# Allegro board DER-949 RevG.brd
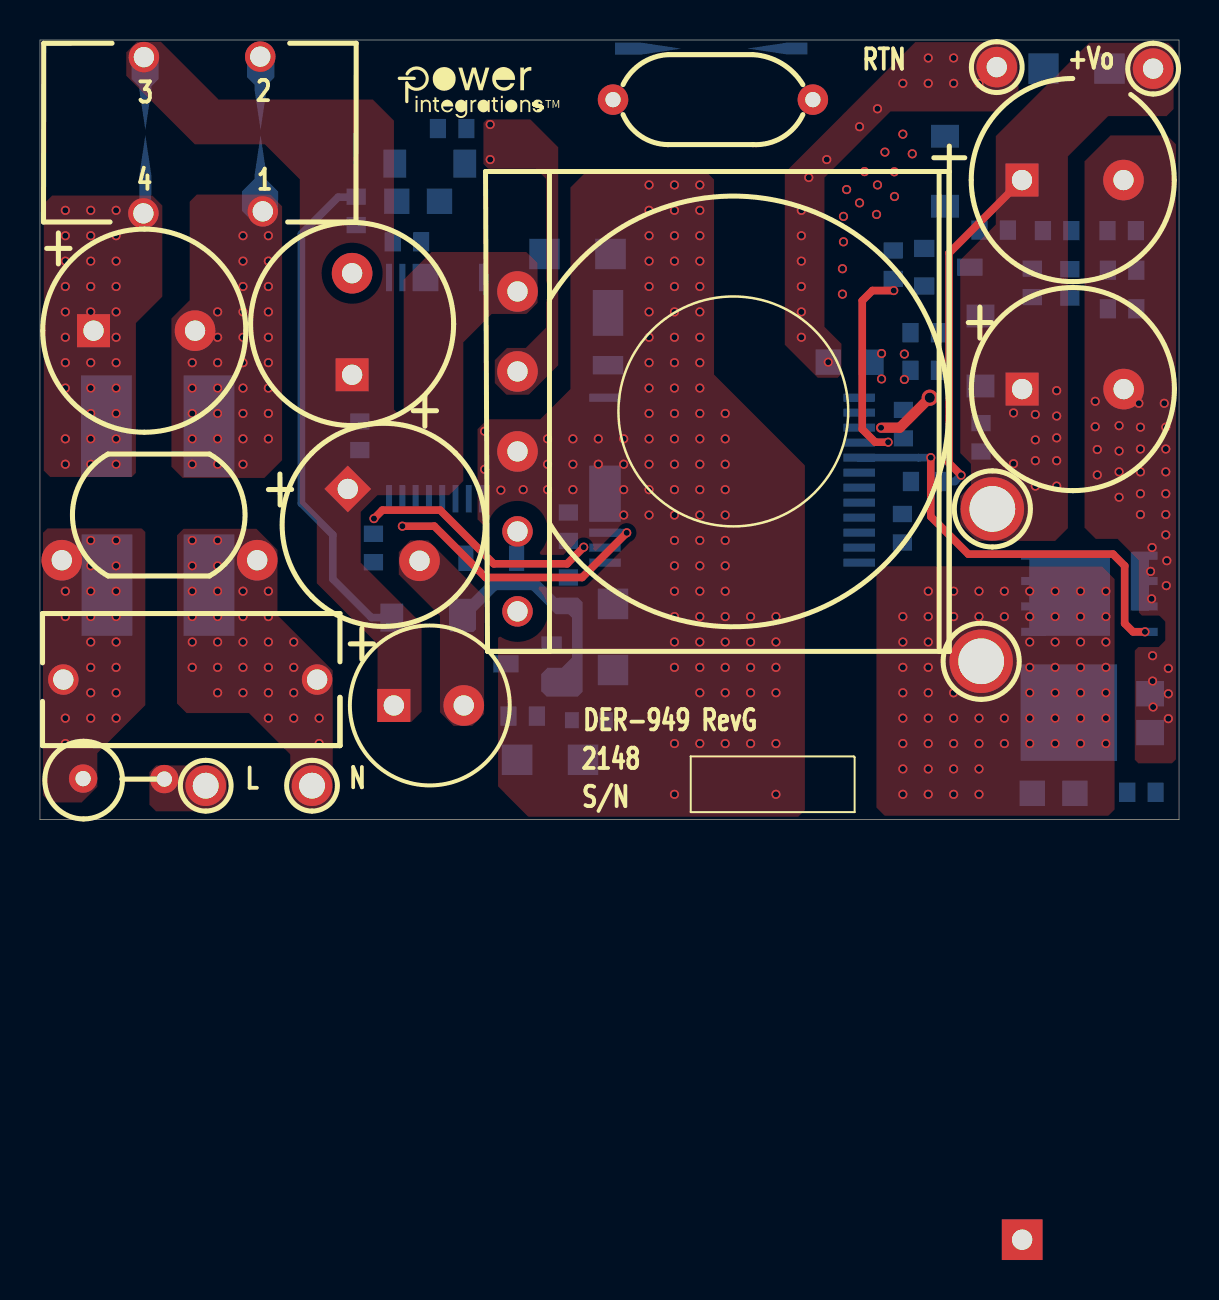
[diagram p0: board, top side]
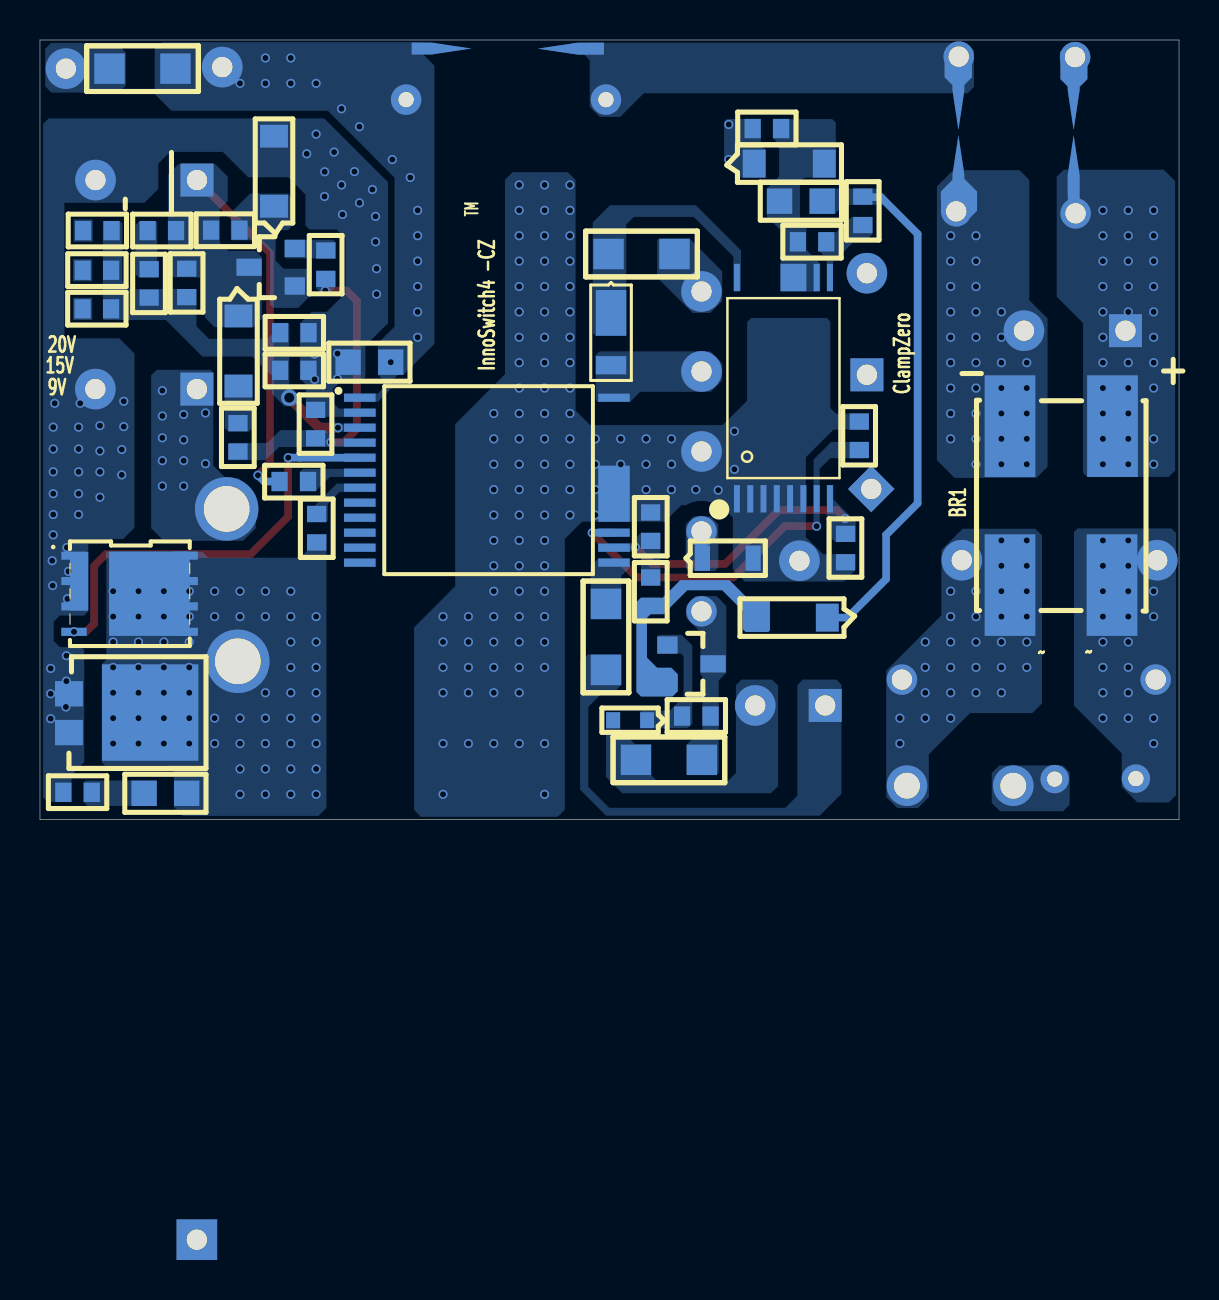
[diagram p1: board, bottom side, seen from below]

Outline 57 x 39 mm; copper layers: TOP, INNER1, INNER2, BOTTOM. Coordinates in mm from the lower left corner of the outline.
Outline path: 0,39 0,0 57,0 57,39 0,39

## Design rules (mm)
constraint set DEFAULT: min track width 0.508

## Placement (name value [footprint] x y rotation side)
BR1  Z4DGP406L-HF  [PI_SM_D_Z4D]  3.35 19.74 180 bottom
C1  150 nF  [PINPXCAPRAD475X255500040]  13.87 7.01 180 top
C2  27 uF  [PIPOLCAPCYLD400LS200040]  15.4 16.54 315 top
C3  27 uF  [PIPOLCAPCYLD400LS200040]  15.62 22.25 90 top
C4  27 uF  [PIPOLCAPCYLD400LS200040]  2.68 24.46 0 top
C5  0.47 uF  [PISMC0603]  26.44 13.94 90 bottom
C6  10 uF  [PISMC1206]  23.88 3 0 bottom
C7  2200 pF  [PINPCAPRAD9MMXLS10MM030]  28.68 36.02 0 top
C8  1000 pF  [PISMC0603]  54.41 1.37 0 bottom
C9  2.2 uF  [PISMC0603]  43.21 20.5 270 bottom
C11  330 pF  [PISMC0603]  44.98 24.36 180 bottom
C12  47 nF  [PISMC0603]  51.54 27.54 270 bottom
C13  10 uF  [PISMC1206]  53.52 37.57 180 bottom
C14  390 uF  [PIPOLCAPCYLD400LS200040]  49.14 31.99 0 top
C15  390 uF  [PIPOLCAPCYLD400LS200040]  49.15 21.54 0 top
C18  100 nF  [PISMC1206]  25.25 28.3 0 bottom
C33  4.7 nF  [PISMC0603]  19.91 34.57 0 bottom
C34  1 uF  [PISMC0805]  19.99 30.94 180 bottom
C35  100 nF  [PISMC0603]  17.65 28.91 0 bottom
C36  100 nF  [PISMC0603]  16.69 14.3 270 bottom
C44  12 uF  [PIPOLCAPCYLD3P5LS17LD40]  19.51 5.71 0 top
D1  DFLU1400-7  [PISMDDFLR120012]  28.42 25.37 90 bottom
D2  BAV21WS-7-F  [PISMSOD323]  23.85 13.08 180 bottom
D5  DSS12UTR  [PI_SM_SOD-123_12]  21.26 32.82 180 bottom
D6  HS1KFL  [PI_SM_SOD-123_12]  17.6 10.11 0 bottom
D7  V12P10-M3/86A  [PI_SM_D_TO-277A]  55.55 4.34 270 bottom
F1  6.3 A  [PI_V_AX_3-6X10_145LS200D030]  7.24 2.06 180 top
FL1  Hole_70mils  [PI_HOLE_70MIL]  47.66 15.52 0 top
FL2  Hole_70mils  [PI_HOLE_70MIL]  47.1 7.9 0 top
L1  18mH  [PI_CMC_18MH_SUMIDA]  11.15 30.1 180 top
NOREF  -  []  17.35 37.57 0 top
NOREF#2  -  []  0 0 90 top
NOREF#3  -  []  0 39 0 top
NOREF#4  -  []  -228.6 -144.78 0 top
NOREF#5  -  []  -150.78 54.23 0 top
Q1  MMBTA06LT1G  [PISMSOT23123_1]  25.6 6.86 270 bottom
Q4  AON6220  [PISMPQFN5X6B]  55.3 13.21 270 bottom
Q5  MMBTA06LT1G  [PISMSOT23123_1]  44.25 28.57 90 bottom
R9  3 k  [PISMR0603]  15.82 31.17 270 bottom
R10  47  [PISMR0603]  43.15 13.87 90 bottom
R12  2 k  [PISMR0603]  26.44 10.69 90 bottom
R13  0.0  [PISMR0805]  49.66 1.32 0 bottom
R14  100 k  [PISMR0603]  49.66 27.56 270 bottom
R15  33 K  [PISMR0603]  44.99 22.48 180 bottom
R16  0.005  [PISMR0805]  41.58 22.89 180 bottom
R19  2.7 M  [PISMR1206]  28.68 10.79 270 bottom
R22  32.4 k  [PISMR0603]  53.44 25.55 0 bottom
R23  12.7 k  [PISMR0603]  53.44 27.48 0 bottom
R24  10 k  [PISMR0603]  50.19 29.46 0 bottom
R25  1.2 k  [PISMR0603]  47.09 19.84 270 bottom
R27  8.45 k  [PISMR0603]  53.42 29.46 0 bottom
R29  75 k  [PISMR0603]  23.44 5.18 0 bottom
R31  20 k  [PISMR0603]  48.44 29.49 180 bottom
R32  47  [PISMR0603]  42.7 28.47 270 bottom
R33  30 k  [PISMR0603]  16 19.91 270 bottom
R34  100  [PISMR0603]  45.01 16.92 180 bottom
RV1  175 Vac  [PI_DISC_335X240LS200D040]  8.48 17.53 180 top
T1  EQ25  [PI_BOBBIN_EQ-25_6P]  34.7 20.42 0 top
TP1  BLK  [PITPKEYSTONE100X100]  13.61 1.7 0 top
TP2  WHT  [PITPKEYSTONE100X100]  8.29 1.7 0 top
TP10  BLK  [PITPKEYSTONE100X100]  47.88 37.64 0 top
TP11  RED  [PITPKEYSTONE100X100]  55.7 37.57 0 top
U3  CPZ1062M  [PI_SM_MINSOP16A_1]  22.12 16.05 180 bottom
U4  INN4075C-H182  [PI_IC_INSOP_24D_IPC]  41 21.11 180 bottom
VR1  MMSZ5250B-7-F  [PI_SM_SOD-123_12]  47.07 25.2 270 bottom
VR4  EDZVT2R10B  [PI_SM_D_SSMINI2P]  26.62 4.98 0 bottom
VR5  MMSZ5232B-7-F  [PI_SM_SOD-123_12]  45.29 30.68 90 bottom

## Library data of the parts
BR1 = DISCRETE BRIDGE_+~~-
C1 C5 C7 C8 C11-C13 C18 = CAP NP
C2-C4 = CAP POL: alternate symbols: (pipolcapclyd400x675ls200040h)
C6 = CAP NP: alternate symbols: (pismc1206_1)
C9 = CAP NP: alternate symbols: (pismc0603_1)
C14 C15 = CAP POL: alternate symbols: (pipolcapclyd400x530ls200030h)
C33-C36 = CAP NP: room: 2
C44 = CAP POL: alternate symbols: (pipolcapcyld3p5ls17ld40H)
D1 D2 = DIODE
D5 = DIODE SCHOTTKY
D6 = DIODE: room: 2
D7 = DIODE SCHOTTKY_TO-277A
F1 = FUSE: alternate symbols: (pi_axial_3_6x10_145ls500d030)
FL1 FL2 = FlyingLead
L1 = TORRID 4P_12_43a: alternate symbols: (pi_CMC_18mH_SumidaW,pi_CMC_18mH_Sumida_H,pi_CMC_18mH_SumidaSF)
Q1 Q5 = NPN_BEC: room: 2
Q4 = FET_N_SGD_123_4_5678
R9 R29 R31 R33 R34 = R: room: 2
R10 = R: alternate symbols: (pismr0603_1)
R12 R32 = R: alternate symbols: (pismr0603_1); room: 2
R13 = R: alternate symbols: (pismr0805_1)
R14-R16 R19 R22-R25 R27 = R
RV1 = VARISTOR
T1 = BEQ25_6P
TP1 TP10 = TESTPOINT: alternate symbols: (TP_TH_CR2_D1_1)
TP2 TP11 = TESTPOINT
U3 = ClampZeroMinSOP16: room: 2
U4 = MinnoPriSecCZ: alternate symbols: (pi_ic_insop_24d,PI_IC_INSOP24B)
VR1 = DIODE_ZENER
VR4 VR5 = DIODE_ZENER: room: 2

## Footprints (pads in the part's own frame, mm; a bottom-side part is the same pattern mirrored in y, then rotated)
PI_BOBBIN_EQ-25_6P
  rect 2.032x2.032 hole 1.016: 1(14.453,-41.427)
  round 2.032 hole 1.016: 2(-10.8,6) 3(-10.8,2) 4(-10.8,-2)
  round 1.524 hole 1.016: 5(-10.8,-6) 6(-10.8,-10)
PI_CMC_18MH_SUMIDA
  round 1.524 hole 1.016: 1(0,-0.33) 2(0.127,-8.068) 3(5.949,-8.043) 4(5.975,-0.229)
PI_DISC_335X240LS200D040
  round 2.032 hole 1.016: 1(-2.388,4.547) 2(7.391,4.547)
PI_HOLE_70MIL
  round 3.175 hole 2.286: 1(0,0.025)
PI_IC_INSOP_24D_IPC
  rect 1.58x0.41 smd: 1(0,0) 2(0,-0.75) 3(0,-1.5) 4(0,-2.25) 5(0,-3) 6(0,-3.75) 7(0,-4.5) 8(0,-5.25) 9(0,-6) 10(0,-6.75) 11(0,-7.5) 12(0,-8.25) 13(12.72,-8.25) 14(12.72,-7.5) 15(12.72,-6.75) 24(12.72,0)
  rect 1.58x2.81 smd: 16(12.72,-4.8)
PI_SM_D_SSMINI2P
  rect 0.699x0.8 smd: 1(0,0) 2(1.7,0)
PI_SM_D_TO-277A
  rect 1.27x1.397 smd: 1(-0.015,0) 2(-1.956,0)
  rect 4.826x4.826 smd: 3(-1.016,4.064)
PI_SM_D_Z4D
  rect 2.54x5.08 smd: 1(0.025,-0.051) 2(0,-8.001) 3(-5.105,-8.001) 4(-5.105,-0.051)
PI_SM_MINSOP16A_1
  rect 0.3x1.37 smd: 1(0,0) 2(0.665,0) 3(1.33,0) 4(1.995,0) 5(2.66,0) 6(3.325,0) 7(3.99,0) 8(4.655,0) 9(4.655,11.067) 10(3.99,11.067) 16(0,11.067)
  rect 1.292x1.37 smd: 11(2.829,11.067)
PI_SM_SOD-123_12
  rect 1.143x1.397 smd: 1(0,0) 2(3.505,0)
PI_V_AX_3-6X10_145LS200D030
  round 1.422 hole 0.762: 1(1.016,0.025) 2(5.08,0)
PINPCAPRAD9MMXLS10MM030
  round 1.524 hole 0.762: 1(0,0) 2(10,0)
PINPXCAPRAD475X255500040
  round 1.524 hole 1.016: 1(0,0) 2(12.7,0)
PIPOLCAPCYLD3P5LS17LD40
  rect 1.651x1.651 hole 1.016: 1(-1.8,0)
  round 2.032 hole 1.016: 2(1.7,0)
PIPOLCAPCYLD400LS200040
  rect 1.651x1.651 hole 1.016: 1(0,0)
  round 2.032 hole 1.016: 2(5.08,0)
PISMC0603
  rect 0.813x0.965 smd: 1(0,0) 2(1.422,0)
PISMC0805
  rect 1.27x1.27 smd: 1(0,0) 2(2.134,0)
PISMC1206
  rect 1.524x1.524 smd: 1(0,0) 2(3.302,0)
PISMDDFLR120012
  rect 2.286x1.524 smd: 1(-0.025,0)
  rect 0.914x1.524 smd: 2(-2.642,0)
PISMPQFN5X6B
  rect 0.406x1.27 smd: 1(0,0) 2(1.27,0) 3(2.54,0) 4(3.81,0)
  rect 0.406x1.219 smd: 5(3.81,5.588) 6(2.54,5.588) 7(1.27,5.588) 8(0,5.588)
PISMR0603
  rect 0.813x0.965 smd: 1(0,0) 2(1.422,0)
PISMR0805
  rect 1.27x1.27 smd: 1(0,0) 2(2.134,0)
PISMR1206
  rect 1.524x1.524 smd: 1(0,0) 2(3.302,0)
PISMSOD323
  rect 0.762x1.27 smd: 1(0,0) 2(2.54,0)
PISMSOT23123_1
  rect 0.864x1.016 smd: 1(-1.88,0) 2(0,0)
  rect 0.864x1.27 smd: 3(-0.94,2.286)
PITPKEYSTONE100X100
  round 2.032 hole 1.016: 1(0,0)

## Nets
GND_POWER: C8.2 C9.1 C11.2 C14.2 C15.2 D7.1 D7.2 Q4.1 Q4.2 Q4.3(S3) R15.2 R16.1 U4.2 VR5.2
GND_SIGNAL: C2.2 C3.2 C5.2 C6.2 C7.1 C36.2 C44.2 D2.2 L1.2 R33.1 T1.4 U3.1 U3.2 U3.3 U3.4 U3.5 U3.6 U4.16 VR4.2
N11018979: C13.1 C14.1 C15.1 FL1.1 Q5.3 R14.1 R24.1 R31.1 R34.1 TP11.1 VR1.1
N11018991: C7.2 C13.2 R16.2 TP10.1 U4.1
N11019027: D7.3(CATHODE) FL2.1 Q4.5 Q4.6 Q4.7 Q4.8 R10.1 R13.1
N11019153: C18.2 D1.1 U3.16
N11019263: BR1.4 C4.2 L1.1
N11019397: BR1.3(AC2) C1.1 RV1.1 TP1.1
N11019401: C8.1 R13.2
N11019625: C2.1 C3.1 C18.1 C44.1 L1.3 R19.2 T1.2
N11019673: BR1.2 C1.2 F1.2 RV1.2
N11019681: BR1.1 C4.1 L1.4
N11019743: C11.1 C12.2 R14.2 R15.1 R22.1 R23.1 R27.1 U4.3
N11020753: C33.2 D1.2 D5.1 T1.3 U4.24
N11026403: F1.1 TP2.1
N11096846: R22.2
N11102317: R23.2
N11111738: C12.1 R24.2
N11114484: R25.1 VR1.2
N12700264: R27.2
N12705759: D2.1 T1.5
N12706342: C6.1 Q1.3 R29.1 T1.6
N12717194: R19.1 U4.13
N12732567: Q4.4 U4.5
N12733996: R10.2 U4.7
N12734050: C9.2 R25.2 R32.2 U4.4
N12734238: R34.2 U4.6
N12735016: C5.1 C36.1 R12.2 U3.8 U4.14
N12739704: Q1.1 R29.2 VR4.1
N12739734: D6.2 Q1.2(EMITTER) R12.1
N13029584: Q5.1 R31.2 VR5.1
N13029614: Q5.2(EMITTER) R32.1
N13041937: C33.1 C34.1 C35.2 D5.2 U3.10 U3.11
N13042085: C35.1 R9.2 U3.9
N13042117: C34.2 D6.1 R9.1
N13042133: R33.2 U3.7 U4.15

Pads without a net: T1 1; U4 8 9 10 11 12

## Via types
v1: diameter 0.457, hole 0.305, TOP to BOTTOM, 362 vias
v2: diameter 0.813, hole 0.508, TOP to BOTTOM, 1 via

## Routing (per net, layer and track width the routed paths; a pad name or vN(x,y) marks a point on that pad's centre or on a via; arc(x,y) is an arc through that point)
GND_POWER:
  vias: v1(40.21,30.18) v1(40.21,28.91) v1(40.16,27.56) v1(40.16,26.29) v1(40.36,31.52) v1(41.01,30.85) v1(41.26,32.42) v1(41.91,31.75) v1(41.86,30.27) v1(42.11,23.32) v1(42.11,22.05) v1(42.28,33.39) v1(42.75,32.41) v1(42.76,31.17) v1(43.18,34.29) v1(43.26,23.29) v1(43.26,22.02) v1(43.65,33.31) v1(52.81,20.93) v1(52.81,19.66) v1(52.91,18.52) v1(52.91,17.25) v1(54,19.71) v1(54,18.44) v1(54,17.4) v1(54,16.13) v1(54.99,20.83) v1(55.07,19.63) v1(55.07,18.54) v1(55.07,17.4) v1(55.07,16.31) v1(55.07,15.27) v1(55.58,12.42) v1(55.63,11.05) v1(55.65,13.61) v1(55.68,8.2) v1(55.68,6.93) v1(55.7,5.64) v1(56.26,20.83) v1(56.34,19.63) v1(56.34,18.54) v1(56.34,17.4) v1(56.34,16.31) v1(56.34,15.27) v1(56.34,14.25) v1(56.39,12.95) v1(56.36,11.71) v1(56.46,7.57) v1(56.46,6.3) v1(56.46,5.05)
GND_SIGNAL:
  vias: v1(22.25,19.43) v1(22.25,17.53) v1(23.06,16.48) v1(24.18,16.51) v1(25.4,19.05) v1(25.4,17.78) v1(25.4,16.51) v1(26.67,19.05) v1(26.67,17.78) v1(26.67,16.51) v1(27.94,19.05) v1(27.94,17.78) v1(29.21,19.05) v1(29.21,17.78) v1(29.21,16.51) v1(29.21,15.24) v1(30.48,31.75) v1(30.48,30.48) v1(30.48,29.21) v1(30.48,27.94) v1(30.48,26.67) v1(30.48,25.4) v1(30.48,24.13) v1(30.48,22.86) v1(30.48,21.59) v1(30.48,20.32) v1(30.48,19.05) v1(30.48,17.78) v1(30.48,16.51) v1(30.48,15.24) v1(31.75,31.75) v1(31.75,30.48) v1(31.75,29.21) v1(31.75,27.94) v1(31.75,26.67) v1(31.75,25.4) v1(31.75,24.13) v1(31.75,22.86) v1(31.75,21.59) v1(31.75,20.32) v1(31.75,19.05) v1(31.75,17.78) v1(31.75,16.51) v1(31.75,15.24) v1(31.75,13.97) v1(31.75,12.7) v1(31.75,11.43) v1(31.75,10.16) v1(31.75,8.89) v1(31.75,7.62) v1(31.75,3.81) v1(31.75,1.27) v1(33.02,31.75) v1(33.02,30.48) v1(33.02,29.21) v1(33.02,27.94) v1(33.02,26.67) v1(33.02,25.4) v1(33.02,24.13) v1(33.02,22.86) v1(33.02,21.59) v1(33.02,20.32) v1(33.02,19.05) v1(33.02,17.78) v1(33.02,16.51) v1(33.02,15.24) v1(33.02,13.97) v1(33.02,12.7) v1(33.02,11.43) v1(33.02,10.16) v1(33.02,8.89) v1(33.02,7.62) v1(33.02,6.35) v1(33.02,3.81) v1(34.29,20.32) v1(34.29,19.05) v1(34.29,17.78) v1(34.29,16.51) v1(34.29,15.24) v1(34.29,13.97) v1(34.29,12.7) v1(34.29,11.43) v1(34.29,10.16) v1(34.29,8.89) v1(34.29,7.62) v1(34.29,6.35) v1(34.29,3.81) v1(35.56,10.16) v1(35.56,8.89) v1(35.56,7.62) v1(35.56,6.35) v1(35.56,3.81) v1(36.83,10.16) v1(36.83,8.89) v1(36.83,7.62) v1(36.83,6.35) v1(36.83,3.81) v1(36.83,1.27)
N11018979: length 17.7
  TOP w0.381: C14.1 45.49,28.34 45.49,17.83 v1(46.09,17.23)
  BOTTOM w0.381: R34.1 45.78,16.92 v1(46.09,17.23)
  vias: v1(48.72,20.35) v1(48.72,17.81) v1(49.81,20.27) v1(49.81,19) v1(49.81,17.96) v1(49.81,16.69) v1(50.88,21.46) v1(50.88,20.19) v1(50.88,19.1) v1(50.88,17.96) v1(50.88,16.69)
N11018991:
  vias: v1(38.1,30.48) v1(38.1,29.21) v1(38.1,27.94) v1(38.1,26.67) v1(38.1,25.4) v1(38.1,24.13) v1(38.47,32.12) v1(39.37,33.02) v1(39.45,22.89) v1(41.01,34.66) v1(41.91,35.56) v1(43.18,36.83) v1(44.45,38.1) v1(44.45,36.83) v1(45.72,38.1) v1(45.72,36.83) v1(46.99,36.83)
N11019027:
  vias: v1(43.18,10.16) v1(43.18,8.89) v1(43.18,7.62) v1(43.18,6.35) v1(43.18,5.08) v1(43.18,3.81) v1(43.18,2.54) v1(43.18,1.27) v1(44.45,11.43) v1(44.45,10.16) v1(44.45,8.89) v1(44.45,7.62) v1(44.45,6.35) v1(44.45,5.08) v1(44.45,3.81) v1(44.45,2.54) v1(44.45,1.27) v1(45.72,11.43) v1(45.72,10.16) v1(45.72,6.35) v1(45.72,5.08) v1(45.72,3.81) v1(45.72,2.54) v1(45.72,1.27) v1(46.99,11.43) v1(46.99,10.16) v1(46.99,5.08) v1(46.99,3.81) v1(46.99,2.54) v1(46.99,1.27) v1(48.26,11.43) v1(48.26,10.16) v1(48.26,5.08) v1(48.26,3.81) v1(49.53,11.43) v1(49.53,10.16) v1(49.53,8.89) v1(49.53,7.62) v1(49.53,6.35) v1(49.53,5.08) v1(49.53,3.81) v1(50.8,11.43) v1(50.8,10.16) v1(50.8,8.89) v1(50.8,7.62) v1(50.8,6.35) v1(50.8,5.08) v1(50.8,3.81) v1(52.07,11.43) v1(52.07,10.16) v1(52.07,8.89) v1(52.07,7.62) v1(52.07,6.35) v1(52.07,5.08) v1(52.07,3.81) v1(53.34,11.43) v1(53.34,10.16) v1(53.34,8.89) v1(53.34,7.62) v1(53.34,6.35) v1(53.34,5.08) v1(53.34,3.81)
N11019263:
  vias: v1(7.62,22.86) v1(7.62,21.59) v1(7.62,20.32) v1(7.62,19.05) v1(7.62,17.78) v1(8.89,25.4) v1(8.89,24.13) v1(8.89,22.86) v1(8.89,21.59) v1(8.89,20.32) v1(8.89,19.05) v1(8.89,17.78) v1(10.16,29.21) v1(10.16,27.94) v1(10.16,26.67) v1(10.16,25.4) v1(10.16,24.13) v1(10.16,22.86) v1(10.16,21.59) v1(10.16,20.32) v1(10.16,19.05) v1(10.16,17.78) v1(11.43,29.21) v1(11.43,27.94) v1(11.43,26.67) v1(11.43,25.4) v1(11.43,24.13) v1(11.43,22.86) v1(11.43,21.59) v1(11.43,20.32) v1(11.43,19.05)
N11019397:
  vias: v1(7.62,13.97) v1(7.62,12.7) v1(7.62,11.43) v1(7.62,10.16) v1(7.62,8.89) v1(7.62,7.62) v1(8.89,13.97) v1(8.89,12.7) v1(8.89,11.43) v1(8.89,10.16) v1(8.89,8.89) v1(8.89,7.62) v1(8.89,6.35) v1(10.16,11.43) v1(10.16,10.16) v1(10.16,8.89) v1(10.16,7.62) v1(10.16,6.35) v1(11.43,11.43) v1(11.43,10.16) v1(11.43,8.89) v1(11.43,7.62) v1(11.43,6.35) v1(11.43,5.08) v1(12.7,8.89) v1(12.7,7.62) v1(12.7,6.35) v1(12.7,5.08) v1(13.97,5.08) v1(13.97,3.81)
N11019673:
  vias: v1(1.27,11.43) v1(1.27,10.16) v1(1.27,5.08) v1(1.27,3.81) v1(2.54,13.97) v1(2.54,12.7) v1(2.54,11.43) v1(2.54,10.16) v1(2.54,8.89) v1(2.54,7.62) v1(2.54,6.35) v1(2.54,5.08) v1(3.81,13.97) v1(3.81,12.7) v1(3.81,11.43) v1(3.81,10.16) v1(3.81,8.89) v1(3.81,7.62) v1(3.81,6.35) v1(3.81,5.08)
N11019681:
  vias: v1(1.27,30.48) v1(1.27,29.21) v1(1.27,27.94) v1(1.27,26.67) v1(1.27,25.4) v1(1.27,24.13) v1(1.27,22.86) v1(1.27,21.59) v1(1.27,19.05) v1(1.27,17.78) v1(2.54,30.48) v1(2.54,29.21) v1(2.54,27.94) v1(2.54,26.67) v1(2.54,25.4) v1(2.54,22.86) v1(2.54,21.59) v1(2.54,20.32) v1(2.54,19.05) v1(2.54,17.78) v1(3.81,30.48) v1(3.81,29.21) v1(3.81,27.94) v1(3.81,26.67) v1(3.81,25.4) v1(3.81,24.13) v1(3.81,22.86) v1(3.81,21.59) v1(3.81,20.32) v1(3.81,19.05) v1(3.81,17.78)
N11019743: length 3.1
  TOP w0.508: v2(44.53,21.11) 43.03,19.61 v1(42.09,19.61)
N11020753:
  vias: v1(22.53,34.77) v1(22.53,33.02)
N12732567: length 21.3
  TOP w0.381: v1(44.58,18.11) 44.58,15.16 46.46,13.28 53.7,13.28 54.28,12.7 54.28,9.82 54.7,9.4 v1(55.3,9.4)
  BOTTOM w0.381: U4.5 43.98,18.11 43.98,18.11 v1(44.58,18.11)
N12734050: length 9.8
  TOP w0.381: v1(42.44,18.88) 41.8,18.88 41.15,19.53 41.15,25.96 41.66,26.47 v1(42.72,26.47)
N12735016: length 12.1
  TOP w0.381: v1(16.71,15.06) 17.14,15.48 20.02,15.48 22.71,12.8 26.38,12.8 v1(27.21,13.63)
N13042117: length 25.2
  BOTTOM w0.381: D6.1 16.59,10.11 14.66,12.04 14.66,14.25 13.08,15.82 13.08,29.3 14.92,31.14 15.8,31.14 R9.1
N13042133: length 14.3
  TOP w0.381: v1(29.36,14.35) 27.13,12.12 22.3,12.12 19.74,14.68 v1(18.14,14.68)
  BOTTOM w0.381: U4.15 29.36,14.36 v1(29.36,14.35)

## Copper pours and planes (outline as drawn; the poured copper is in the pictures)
GND_POWER on BOTTOM (solid shape): 55.5,10.46 54.58,10.46 54.58,13.39 55.5,13.39
GND_POWER on TOP: 56.4,34.23 56.85,33.78 56.85,3.02 56.64,2.82 54.97,2.82 54.79,3 54.79,8.46 54.97,8.64 55.98,8.64 56.31,8.97 56.31,9.91 56.01,10.21 55.14,10.21 54.99,10.36 54.99,12.98 53.92,14.05 52.83,14.05 52.27,14.61 52.27,32.93 53.57,34.23
GND_POWER on BOTTOM: 42.77,35.08 56.57,35.08 56.85,34.8 56.85,1.12 56.62,0.89 55.42,0.89 55.42,2.24 54.79,2.88 54.79,8.48 54.94,8.64 56.01,8.64 56.31,8.94 56.31,9.91 56.01,10.21 54.79,10.21 54.58,10.42 54.58,13.83 54.37,14.04 52.84,14.04 52.27,14.61 52.27,23.32 53.04,24.08 55.78,24.08 55.78,30.86 51.77,30.86 51.08,31.55 51.08,32.82 50.5,33.4 47.85,33.4 46.58,32.13 44.58,32.13 43.71,31.27 43.71,29.72 43.51,29.51 42.14,29.51 41.71,29.08 41.71,26.34 42.65,25.4 43.41,25.4 43.99,24.81 43.99,22.05 43.97,22.05 43.69,21.77 43.69,20.15 40.21,20.15 40.21,20.56 42.05,20.56 42.34,20.85 42.34,21.54 41.99,21.89 40.97,21.89 40.72,22.15 40.72,23.7 39.59,24.83 39.59,31.89
GND_POWER on INNER1: 45.77,35.1 45.77,35.09 45.95,34.92 45.95,33.33 41.7,29.08 41.7,26.34 42.64,25.4 43.41,25.4 43.98,24.83 43.98,22.06 43.49,21.56 41.33,21.56 40.71,22.18 40.71,23.7 39.58,24.83 39.58,31.91 42.77,35.1
GND_POWER on INNER1: 54.97,8.64 56,8.64 56.31,8.95 56.31,9.91 56.01,10.21 54.8,10.21 54.58,10.43 54.58,14.28 54.38,14.47 52.66,14.47 52.27,14.86 52.27,32.93 53.57,34.23 56.4,34.23 56.85,33.79 56.85,3.02 56.64,2.82 54.96,2.82 54.79,3 54.79,8.46
GND_POWER on INNER2: 39.59,31.91 42.77,35.1 45.76,35.1 45.94,34.92 45.94,33.32 41.7,29.08 41.7,26.34 42.64,25.4 43.41,25.4 43.99,24.82 43.99,22.07 43.48,21.56 41.3,21.56 40.72,22.15 40.72,23.7 39.59,24.83
GND_POWER on INNER2: 56.85,33.79 56.85,3.02 56.65,2.82 54.85,2.82 54.79,2.88 54.79,8.41 54.79,8.48 54.94,8.64 56,8.64 56.31,8.95 56.31,9.91 56.01,10.21 54.8,10.21 54.58,10.43 54.58,12.56 54.58,12.56 54.58,14.28 54.39,14.47 52.67,14.47 52.27,14.87 52.27,32.92 53.58,34.23 56.41,34.23
GND_SIGNAL on BOTTOM (solid shape): 32.08,38.57 30.08,38.27 30.1,38.26 28.79,38.26 28.78,38.28 28.78,38.86 28.78,38.87 30.08,38.87
GND_SIGNAL on BOTTOM (solid shape): 11.73,38.43 11.73,37.13 11.34,36.74 11.34,36.5 11.04,34.5 10.74,36.5 10.74,36.75 10.36,37.13 10.36,38.4 10.57,38.61 11.56,38.61
GND_SIGNAL on TOP: 22.23,5.29 21.63,4.69 20.7,4.69 20.02,5.38 20.02,10.2 17.95,12.27 17.95,13.39 18.54,13.97 19.43,13.97 22.23,11.17
GND_SIGNAL on TOP: 25.03,20.03 26.54,21.54 26.54,31.62 27.3,32.38 33.37,32.38 33.73,32.02 33.73,22.26 38.28,17.72 38.28,0.48 37.95,0.15 24.43,0.15 22.92,1.66 22.92,14 21.89,15.02 21.89,19.53 22.39,20.03
GND_SIGNAL on BOTTOM: 29.49,35.65 29.49,38 29.79,38.3 29.79,38.71 29.64,38.86 10.63,38.86 10.26,38.49 10.26,36.65 10.58,36.33 26.78,36.33 27.97,35.15 28.99,35.15
GND_SIGNAL on BOTTOM: 30.2,20.47 30.2,32 30.58,32.38 33.35,32.38 33.73,32 33.73,22.28 36.22,19.79 36.22,11.68 38.28,9.63 38.28,0.48 37.95,0.15 31.08,0.15 30.73,0.5 30.73,14.05 29.87,14.91 25.73,14.91 24.9,15.74 22.95,15.74 22.33,15.11 22.33,12.52 21.72,11.91 16.76,11.91 16.2,12.47 16.2,13.28 17.82,13.28 18.68,14.15 18.68,18.12 17.42,19.38 17.42,19.38 17.29,19.51 15.52,19.51 15.52,20.32 17.17,20.32 17.45,20.6 17.45,24.92 17.63,25.1 21.42,25.1 21.62,24.9 21.62,20.95 22.84,19.74 29.46,19.74
GND_SIGNAL on BOTTOM: 20.37,7.01 21.89,7.01 22.17,6.73 22.17,2.34 22.66,1.85 26.03,1.85 26.42,2.23 26.42,3.76 27.2,3.76 27.97,4.52 27.97,5.38 28.65,5.38 28.68,5.36 28.68,2.48 28.68,2.47 28.68,2.15 27.86,1.32 20.42,1.32 20.07,1.68 20.07,6.71
GND_SIGNAL on INNER1: 33.73,22.28 38.28,17.73 38.28,0.48 37.95,0.15 20.75,0.15 20.02,0.88 20.02,10.21 19.48,10.74 19.41,10.82 17.95,12.28 17.95,12.28 17.95,13.4 18.54,13.98 18.54,13.98 18.73,14.17 18.73,15.13 18.91,15.32 21.34,15.32 22.1,16.08 22.1,20.24 22.39,20.54 25.54,20.54 26.09,21.09 26.09,31.78 26.7,32.39 33.35,32.39 33.73,32.01
GND_SIGNAL on INNER2: 10.6,38.91 20.29,38.91 20.31,38.9 28.66,38.9 29.47,38.09 29.47,35.6 29.01,35.14 27.94,35.14 27.24,35.84 21.97,35.84 21.61,35.48 21.61,20.96 22.04,20.54 25.54,20.54 26.09,21.09 26.09,31.77 26.7,32.38 33.35,32.38 33.73,32.01 33.73,22.27 38.28,17.73 38.28,0.51 37.92,0.15 20.7,0.15 20.02,0.83 20.02,10.16 17.95,12.23 17.95,13.38 17.95,13.38 18.73,14.16 18.73,15.14 18.21,15.66 18.21,23.65 16.64,25.22 15.04,25.22 13.97,26.29 13.97,28.35 14.01,28.38 14.01,33.31 10.23,37.09 10.23,38.54
N11018979 on TOP: 47.83,34.19 52.5,38.86 56.46,38.86 56.73,38.6 56.73,35.55 56.38,35.19 53.45,35.19 51.44,33.17 51.44,14.58 50.8,13.94 46.89,13.94 46.05,14.78 46.05,16.18 46.58,16.71 46.58,17.81 46.05,18.34 46.05,27.99 47.83,29.77
N11018979 on BOTTOM: 46.2,28.45 47.57,28.45 48.01,28.88 48.01,30.53 47.6,30.94 47.6,32.16 48.23,32.79 50.06,32.79 50.6,32.26 50.6,27.43 50.29,27.13 49.3,27.13 49.3,27.13 49.03,27.13 48.74,26.84 48.74,25.12 48.26,24.64 46.3,24.64 45.9,25.04 45.9,28.14
N11018979 on BOTTOM: 47.04,17.07 47.68,17.07 48.33,17.72 48.33,22.37 48.47,22.5 51.16,22.5 51.44,22.23 51.44,14.58 50.81,13.95 46.83,13.95 46.2,14.58 46.2,16.23
N11018979 on BOTTOM: 53.06,36.37 52.7,36.72 52.7,38.37 53.19,38.85 56.44,38.85 56.74,38.56 56.74,36.68 56.43,36.37
N11018979 on INNER1: 56.73,35.55 56.38,35.19 53.43,35.19 51.43,33.19 51.43,14.55 50.82,13.94 46.88,13.94 46.05,14.78 46.05,16.18 46.58,16.72 46.58,17.81 46.05,18.34 46.05,30.16 47.82,31.93 47.82,34.18 52.5,38.86 56.46,38.86 56.73,38.59
N11018979 on INNER2: 47.83,34.21 52.47,38.85 56.44,38.85 56.73,38.57 56.73,35.54 56.38,35.19 53.43,35.19 51.67,33.43 51.67,33.42 51.43,33.18 51.43,14.56 50.82,13.95 46.88,13.95 46.04,14.78 46.04,16.17 46.58,16.71 46.58,17.81 46.05,18.34 46.05,30.15 47.83,31.92
N11018991 on BOTTOM (solid shape): 38.4,38.27 37.4,38.27 35.4,38.57 37.4,38.87 38.4,38.87
N11018991 on TOP: 48.96,36.46 48.96,38.34 48.41,38.89 43.8,38.89 37.27,32.36 37.27,23.75 38.92,22.1 39.92,22.1 40.11,22.29 40.11,23.8 39.26,24.65 39.26,32.12 42.57,35.43 47.93,35.43
N11018991 on BOTTOM: 39.26,32.12 42.6,35.46 50.42,35.46 51.26,36.3 51.26,38.53 50.9,38.89 37.82,38.89 37.82,38.28 37.26,37.72 37.26,23.8 38.8,22.25 39.09,22.25 39.37,21.97 39.37,21.62 40.08,20.9 41.79,20.9 41.79,20.9 41.79,21.31 41.79,21.31 40.11,21.31 39.8,21.62 39.8,21.97 40.09,22.26 40.09,23.82 39.26,24.66
N11018991 on INNER1: 39.26,32.12 42.57,35.43 47.93,35.43 48.96,36.46 48.96,38.35 48.44,38.86 43.81,38.86 37.27,32.33 37.27,23.75 38.92,22.1 39.92,22.1 40.11,22.29 40.11,23.81 39.26,24.65
N11018991 on INNER2: 39.29,24.62 39.26,24.66 39.26,32.12 42.57,35.43 47.93,35.43 48.97,36.47 48.97,38.34 48.44,38.86 43.81,38.86 37.26,32.31 37.26,23.78 38.89,22.16 39.99,22.16 40.09,22.26 40.09,23.82
N11019027 on BOTTOM (solid shape): 53.54,9.19 49.5,9.19 49.5,13.41 53.54,13.41
N11019027 on TOP: 53.14,12.67 53.77,12.04 53.77,0.51 53.47,0.2 42.27,0.2 41.86,0.61 41.86,12.19 42.34,12.67
N11019027 on BOTTOM: 53.9,7.78 53.9,2.86 53.74,2.7 50.54,2.7 50.29,2.45 50.29,0.64 49.85,0.19 43.07,0.19 42.66,0.59 42.66,14.28 43.64,14.28 43.64,13.44 43.97,13.11 48.59,13.11 48.9,13.41 53.68,13.41 53.68,8
N11019027 on INNER1: 41.86,11.78 42.28,12.2 53.61,12.2 53.77,12.04 53.77,0.51 53.47,0.2 53.47,0.2 42.27,0.2 41.86,0.61
N11019027 on INNER2: 41.86,0.61 41.86,11.78 42.28,12.2 53.62,12.2 53.78,12.04 53.78,0.5 53.48,0.2 42.26,0.2
N11019153 on BOTTOM: 24.18,30.73 28.47,30.73 29.34,29.87 29.34,24.36 29.18,24.21 27.66,24.21 27.66,24.23 27.66,29.77 27.28,30.15 24.28,30.15 22.3,28.17 22.3,26.49 22.25,26.44 21.97,26.44 21.92,26.49 21.92,28.47
N11019263 on BOTTOM (solid shape): 11.34,32.24 11.34,32 11.89,31.46 11.92,31.43 11.92,30.99 11.91,30.99 11.91,30.56 11.48,30.12 10.44,30.12 10.11,30.46 10.11,31.42 10.74,32.05 10.74,32.24 11.04,34.24
N11019263 on TOP: 12.12,30.68 11.53,31.27 7.85,31.27 7.49,30.91 7.49,25.98 6.58,25.07 6.58,17.65 7.14,17.09 11.23,17.09 12.12,17.98
N11019263 on BOTTOM: 12.12,31.67 11.3,32.49 7.98,32.49 7.49,32 7.49,25.98 6.58,25.07 6.58,17.65 7.14,17.09 11.23,17.09 12.12,17.98
N11019263 on INNER1: 11.31,32.48 7.97,32.48 7.48,32 7.48,25.98 6.58,25.07 6.58,17.65 7.14,17.09 11.23,17.09 12.12,17.98 12.12,31.68
N11019263 on INNER2: 11.31,32.48 7.97,32.48 7.48,32 7.48,25.98 6.56,25.05 6.56,17.65 7.13,17.08 11.21,17.08 12.12,17.98 12.12,31.68
N11019397 on TOP: 14.65,1.14 14.1,0.58 13.07,0.58 12.52,1.13 12.52,3.27 10.46,5.33 7.34,5.33 6.86,5.82 6.86,14.22 7.19,14.55 10.83,14.55 11.89,13.5 11.89,10.23 14.65,7.46
N11019397 on BOTTOM: 12.52,1.13 12.52,3.26 10.45,5.33 7.34,5.33 6.86,5.82 6.86,14.22 7.19,14.55 10.83,14.55 11.89,13.49 11.89,10.23 14.65,7.46 14.65,1.14 14.1,0.58 13.06,0.58
N11019397 on INNER1: 12.52,1.11 12.52,3.25 10.44,5.33 7.34,5.33 6.84,5.83 6.84,14.24 7.15,14.55 10.86,14.55 11.94,13.48 11.94,10.17 14.66,7.45 14.66,1.08 14.64,1.08 14.13,0.57 13.06,0.57
N11019397 on INNER2: 12.52,3.25 10.44,5.33 7.34,5.33 6.84,5.83 6.84,14.25 7.14,14.55 10.86,14.55 11.94,13.47 11.94,10.18 14.66,7.46 14.66,1.13 14.1,0.58 13.06,0.58 12.52,1.11
N11019401 on BOTTOM: 54.81,1.85 54.81,0.89 54.61,0.69 51.16,0.69 51.16,1.92 51.2,1.96 54.53,1.96 54.71,1.96
N11019625 on BOTTOM (solid shape): 5.94,38.41 5.94,37.04 5.57,36.68 5.57,36.5 5.27,34.5 4.97,36.5 4.97,36.65 4.58,37.04 4.58,38.54 4.7,38.66 5.69,38.66
N11019625 on TOP: 4.85,38.91 6.05,38.91 8.94,36.02 16.66,36.02 17.71,34.97 17.71,20.52 17.86,20.38 18.04,20.38 18.05,20.38 18.2,20.53 18.2,27.02 19.58,28.4 24.33,28.4 24.9,27.83 24.9,25.86 24.35,25.3 22.61,25.3 21.18,23.88 21.18,17.95 21.19,17.95 21.19,16.94 20.48,16.23 16.89,16.23 16.05,15.39 16.05,12.85 19.1,9.81 19.1,5.4 18.59,4.89 16.89,4.89 16.89,4.89 16.89,8.79 13.86,11.82 13.86,14.97 13,15.82 13,32.03 11.25,33.78 7.75,33.78 4.32,37.21 4.32,38.38
N11019625 on BOTTOM: 27.91,8.27 29.57,8.27 29.97,7.87 29.97,1.5 28.67,0.2 17.98,0.2 16.89,1.3 16.89,6.76 17.14,7.01 18.82,7.01 19.1,6.73 19.1,1.19 19.7,0.59 28.51,0.59 29.56,1.65 29.56,5.64 28.91,6.3 28.34,6.3 27.91,6.74
N11019625 on BOTTOM: 26.04,29.06 24.49,29.06 22.86,27.43 22.86,25.95 23.46,25.35 24.34,25.35 26.12,27.12 26.12,28.98
N11019625 on INNER1: 19.58,28.4 23.93,28.4 24.92,27.41 24.92,25.98 24.23,25.3 22.61,25.3 21.18,23.88 21.18,16.94 20.47,16.23 16.89,16.23 16.05,15.39 16.05,12.8 19.1,9.76 19.1,5.38 18.71,4.99 16.89,4.99 16.88,4.99 16.88,8.79 13.85,11.82 13.85,14.99 13.01,15.83 13.01,23.03 13.9,23.93 16.35,23.93 16.35,23.92 17.14,23.92 17.71,23.36 17.71,20.53 17.86,20.38 18.05,20.38 18.2,20.53 18.2,27.02
N11019625 on INNER2: 17.06,23.16 17.06,16.4 16.03,15.37 16.03,14.81 16.07,14.77 16.07,12.83 19.09,9.8 19.09,5.41 18.67,4.98 16.89,4.98 16.88,4.99 16.88,8.79 13.86,11.81 13.86,15.02 13,15.88 13,23.01 13.92,23.93 16.29,23.93
N11019673 on TOP: 5.27,5.73 5.27,14.39 5.09,14.57 0.37,14.57 0.15,14.35 0.15,1.22 0.51,0.86 2.08,0.86 2.87,1.65 2.87,3.33
N11019673 on BOTTOM: 2.87,3.33 5.26,5.71 5.26,14.39 5.08,14.57 0.37,14.57 0.15,14.35 0.15,1.22 0.51,0.86 2.08,0.86 2.87,1.65
N11019673 on INNER1: 5.26,5.71 5.26,14.4 5.08,14.57 0.63,14.57 0.37,14.57 0.18,14.39 0.18,1.22 0.53,0.86 2.06,0.86 2.87,1.68 2.87,3.32 4.98,5.44
N11019673 on INNER2: 5.26,5.72 5.26,14.39 5.08,14.57 0.36,14.57 0.15,14.36 0.15,1.22 0.51,0.86 2.08,0.86 2.87,1.65 2.87,3.33
N11019681 on BOTTOM (solid shape): 5.57,32.24 5.57,31.24 5.56,31.24 5.56,30.48 5.41,30.33 5.08,30.33 4.97,30.43 4.97,32.24 5.27,34.24
N11019681 on TOP: 4.8,24.84 6.12,26.16 6.12,30.72 5.62,31.22 0.61,31.22 0.19,30.8 0.19,17.46 0.51,17.14 4.6,17.14 4.8,17.35
N11019681 on BOTTOM: 6.12,26.16 6.12,32.16 5.77,32.51 0.76,32.51 0.19,31.94 0.19,17.46 0.51,17.14 4.6,17.14 4.8,17.35 4.8,24.84
N11019681 on INNER1: 4.8,17.34 4.8,24.84 6.12,26.16 6.12,32.16 5.77,32.51 0.75,32.51 0.68,32.44 0.68,32.42 0.19,31.94 0.19,17.46 0.5,17.15 4.6,17.15
N11019681 on INNER2: 4.8,17.27 4.8,24.84 6.12,26.16 6.12,32.16 5.77,32.51 0.75,32.51 0.68,32.44 0.68,32.42 0.12,31.86 0.12,17.48 0.48,17.12 4.65,17.12
N11019743 on BOTTOM: 44.12,20.85 44.12,21.31 44.53,21.72 44.53,24.79 44.58,24.84 45.39,24.84 45.39,24.28 45.62,24.05 48.54,24.05 49.17,24.69 49.17,26.54 49.18,26.54 52.48,26.54 52.88,26.95 52.88,29.82 53,29.95 53.83,29.95 53.85,29.92 53.85,25.04 53.8,24.99 50.7,24.99 48.87,23.16 46.35,23.16 45.39,22.2 45.39,21.31 44.75,20.68 44.3,20.68
N11020753 on TOP: 22.43,32.56 24.82,32.56 25.32,32.05 25.32,24.61 24.31,23.6 23.37,23.6 22.76,22.99 22.76,21.84 23.34,21.26 24.46,21.26 25.93,22.73 25.93,33.63 24.54,35.03 22.36,35.03 22.19,34.86 22.19,32.8
N11020753 on BOTTOM: 20.93,35.05 22.64,35.05 22.76,34.92 22.76,32.93 21.95,32.11 20.69,32.11 20.69,33.51 20.93,33.75
N11020753 on BOTTOM: 29.19,20.98 29.11,20.9 27.46,20.9 26.96,21.41 23.42,21.41 22.86,21.97 22.86,22.83 23.46,23.43 28.99,23.43 29.19,23.23
N11026403 on TOP: 8.99,2.72 9.37,2.34 9.37,0.84 8.95,0.42 5.8,0.42 5.47,0.75 5.47,2.37 5.82,2.72
N11026403 on BOTTOM: 9.37,2.34 9.37,0.84 8.95,0.42 5.8,0.42 5.47,0.75 5.47,2.37 5.82,2.72 8.99,2.72
N11096846 on BOTTOM: 54.38,24.99 55.35,24.99 55.35,26.11 54.38,26.11
N11102317 on BOTTOM: 54.38,26.92 55.34,26.92 55.34,28.04 54.38,28.04
N11111738 on BOTTOM: 52.22,29.74 52.22,27.3 52.05,27.12 51.13,27.12 51.13,28.27 51.13,28.27 51.13,29.87 51.21,29.94 51.21,29.95 52.02,29.95
N11114484 on BOTTOM: 46.35,22.25 47.76,22.25 47.76,19.59 47.57,19.41 46.56,19.41 46.35,19.61
N12700264 on BOTTOM: 54.36,28.9 55.32,28.9 55.32,30.02 54.36,30.02
N12705759 on BOTTOM: 23.06,14.76 23.46,15.16 24.29,15.16 24.69,14.77 24.69,12.6 24.54,12.45 23.22,12.45 23.06,12.61
N12706342 on BOTTOM: 24.23,11.15 24.65,10.73 24.65,10.08 23.95,9.39 23.95,7.26 23.85,7.16 23.85,4.54 24.64,3.75 24.64,2.26 24.61,2.24 23.16,2.24 23.03,2.36 23.03,6.96 22.66,7.34 22.66,10.69 23.15,11.18 24.2,11.18
N12717194 on BOTTOM: 29.44,12.69 29.44,10.03 27.91,10.03 27.91,12.2 27.48,12.62 27.48,13.06 29.06,13.06
N12733996 on BOTTOM: 42.14,16.81 43.25,15.7 43.63,15.7 43.64,15.7 43.64,14.88 43.64,14.88 42.68,14.88 42.6,14.96 42.6,15.8 41.99,16.4 40.21,16.4 40.21,16.81
N12734050 on BOTTOM: 42.71,19.49 42.72,19.48 44.97,19.48 45.61,18.85 47.55,18.85 47.57,18.82 47.57,17.98 45.69,17.98 45.03,18.64 43.79,18.64 42.62,18.64 40.22,18.64 40.2,18.66 40.2,19.06 42.29,19.06
N12734050 on BOTTOM: 42.24,27.38 42.24,26.59 42.6,26.24 42.85,26.24 43.15,26.54 43.15,27.38
N12734238 on BOTTOM: 40.26,17.55 43.84,17.55 43.99,17.4 43.99,16.43 43.21,16.43 42.49,17.14 40.21,17.14 40.21,17.5
N12735016 on BOTTOM: 16.18,13.89 17.2,13.89 17.63,14.33 17.63,16.74 17.32,16.74 17.3,16.71 17.3,16.03 16.18,14.91
N12735016 on BOTTOM: 29.03,13.82 27.46,13.82 26.92,14.35 25.98,14.35 25.96,14.33 25.96,11.71 26.92,11.71 26.92,13.03 27.3,13.41 29.06,13.41 29.06,13.79
N12739704 on BOTTOM: 26.11,9.15 26.11,8.31 24.92,8.31 24.79,8.18 24.79,6.15 25.48,5.46 26.89,5.46 26.97,5.38 26.97,4.58 24.61,4.58 24.6,4.58 24.57,4.58 24.36,4.8 24.36,8.72 24.88,9.25 26.01,9.25
N12739734 on BOTTOM (solid shape): 25.84,11.1 26.93,11.1 27.15,10.88 27.15,6.39 26.92,6.16 25.35,6.16 25.09,6.42 25.09,7.29 25.4,7.6 26.12,7.6 26.62,8.11 26.62,10.1 26.44,10.28 25.8,10.28 24.61,11.48 22.86,11.48 21.82,10.44 21.82,9.52 21.69,9.39 20.55,9.39 20.47,9.48 20.47,10.91 20.6,11.05 21.57,11.05 22.5,11.98 24.95,11.98
N13029584 on BOTTOM: 44.58,31.32 46.48,31.32 47.45,30.35 47.45,29.01 47.42,28.98 46.04,28.98 45.49,28.43 45.49,25.79 45.3,25.6 44.07,25.6 43.59,26.09 43.59,27.48 43.66,27.56 44.81,27.56 45.21,27.97 45.21,29.29 45.01,29.49 44.59,29.49 44.37,29.7 44.37,31.11
N13029614 on BOTTOM: 44.75,29.01 44.75,28.13 44.69,28.07 42.2,28.07 42.2,28.88 42.33,29.01
N13041937 on BOTTOM: 17.96,26.47 17.96,27.81 18.64,28.5 18.64,29.61 18.97,29.94 18.97,31.88 18.73,32.12 17.18,32.12 17.18,34.87 17.35,35.04 20.32,35.04 20.32,34.09 20.02,33.78 20.02,32.18 20.63,31.57 20.63,30.17 19.94,29.48 19.94,26.42 18.01,26.42
N13042085 on BOTTOM: 17.63,26.47 17.63,28.07 18.06,28.5 18.06,29.39 17.14,29.39 16.38,30.15 15.34,30.15 15.34,30.15 15.34,29.28 15.62,29.01 16.18,29.01 17.32,27.86 17.32,26.47 17.35,26.44 17.6,26.44
N13042117 on BOTTOM: 15.06,31.57 14.63,31.14 14.63,30.83 14.7,30.75 16.77,30.75 17.22,30.3 18.49,30.3 18.49,30.3 18.49,31.54 18.47,31.57
N13042133 on BOTTOM: 18.29,18.01 18.29,14.61 18.21,14.53 18.08,14.53 17.98,14.63 17.98,17.55 17.45,18.08 15.52,18.08 15.52,18.9 17.4,18.9

Small or netless copper shapes (teardrops, artwork), in the pictures only: 1 on BOTTOM

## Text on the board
Ref Des/Silkscreen Bottom: TM | 20V | 9V | 15V | ClampZero | InnoSwitch4 -CZ
User.Comments: 10 | 13 | /16 | 25 | 20 | NG | 7
Ref Des/Silkscreen Top: L | N | 2148 | S/N | DER-949 RevG | RTN | +Vo
User.6: NOTES: DELETE THESE PINS | 14.  FAB HOUSE LOGO,DATE CODE TO BE IN SILK SCREEN ONLY.DO NOT USE COPPER. | 13.  MATERIAL FR4 COPPER 2oz THICKNESS 0.062"
User.9: FIGURE | FINISHED_SIZE | 12.0 | 20.0 | 30.0 | 40.0 | 51.0 | 90.0 | DRILL CHART: TOP to BOTTOM | ALL UNITS ARE IN MILS | TOLERANCE_DRILL | +3.0/-3.0 | PLATED | QTY | 362 | 1 | 4 | 28 | 2
